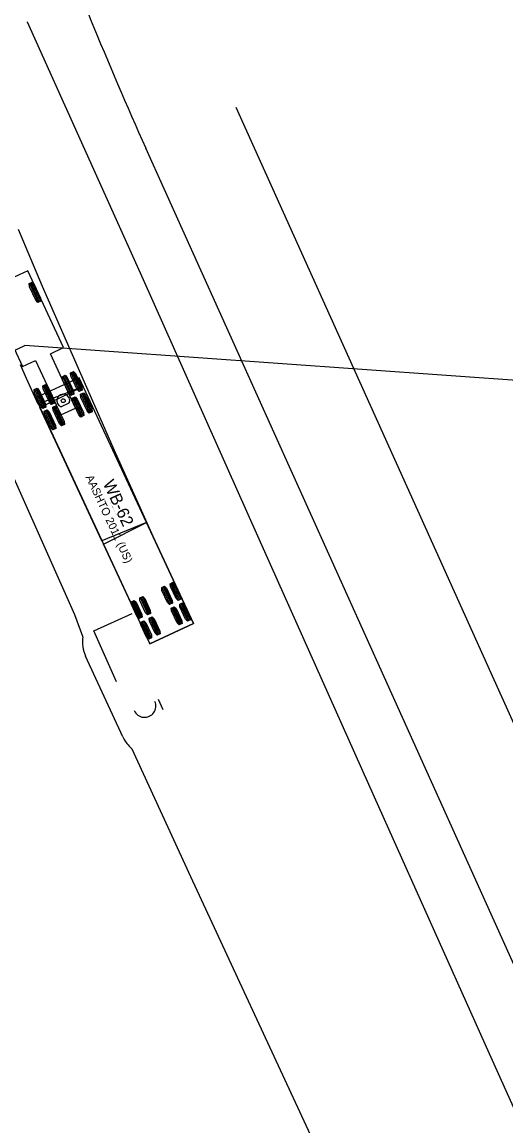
# Model space of a CAD drawing. Extents: x 2096670 to 2098561, y 684033 to 689893.
# Drawn here: x 2097772.9 to 2097858.5, y 685641.1 to 685836.6 of the extents above; entities that cross this region are included whole.
import ezdxf

# ---------------------------------------------------------------- set-up
doc = ezdxf.new("R2010")
doc.units = 0
for name, color, linetype in [('Old_Level_63', 7, 'Continuous'), ('Prop Conc 5in Monolithic Keyed In Island', 7, 'Continuous'), ('Prop DSN Text', 7, 'Continuous'), ('Prop EOT', 7, 'Continuous'), ('Prop Guardrail', 7, 'Continuous'), ('Prop Sign E Signal Light Ahead CELL', 7, 'Continuous'), ('Scratch_Level_4', 7, 'Continuous'), ('Scratch_Level_7', 7, 'Continuous')]:
    doc.layers.add(name, color=color, linetype=linetype)

msp = doc.modelspace()

# ---------------------------------------------------------------- linework, layer by layer
at = {"layer": 'Old_Level_63'}
for p, q in [((2097773.91, 685792.52), (2097766.65, 685789.15)), ((2097780.22, 685778.92), (2097773.91, 685792.52)), ((2097774.19, 685790.27), (2097775.74, 685786.94)), ((2097774.4, 685790.36), (2097775.95, 685787.04)), ((2097774.61, 685790.46), (2097776.15, 685787.13)), ((2097766.65, 685789.15), (2097772.97, 685775.55)), ((2097777.9, 685777.84), (2097780.22, 685778.92)), ((2097772.97, 685775.55), (2097775.3, 685776.63)), ((2097775.3, 685776.63), (2097779.76, 685767.01)), ((2097782.36, 685768.22), (2097777.9, 685777.84)), ((2097781.52, 685774.49), (2097783.07, 685771.16)), ((2097781.73, 685774.58), (2097783.28, 685771.26)), ((2097781.94, 685774.68), (2097783.48, 685771.35)), ((2097782.98, 685773.58), (2097775.27, 685770)), ((2097776.6, 685772.2), (2097778.14, 685768.87)), ((2097776.8, 685772.29), (2097778.35, 685768.97)), ((2097777.01, 685772.39), (2097778.56, 685769.06)), ((2097780.03, 685773.79), (2097781.57, 685770.47)), ((2097780.24, 685773.89), (2097781.78, 685770.56)), ((2097780.44, 685773.98), (2097781.99, 685770.66)), ((2097803.2, 685730.05), (2097782.98, 685773.58)), ((2097775.1, 685771.5), (2097776.64, 685768.18)), ((2097775.31, 685771.6), (2097776.85, 685768.27)), ((2097775.52, 685771.7), (2097777.06, 685768.37)), ((2097783.29, 685770.68), (2097784.84, 685767.35)), ((2097783.5, 685770.77), (2097785.05, 685767.45)), ((2097783.71, 685770.87), (2097785.25, 685767.54)), ((2097775.27, 685770), (2097795.49, 685726.47)), ((2097775.27, 685770), (2097775.27, 685770)), ((2097778.37, 685768.39), (2097779.91, 685765.06)), ((2097778.57, 685768.48), (2097780.12, 685765.16)), ((2097778.78, 685768.58), (2097780.33, 685765.26)), ((2097779.78, 685768.45), (2097781.25, 685769.13)), ((2097781.8, 685769.98), (2097783.34, 685766.66)), ((2097782, 685770.08), (2097783.55, 685766.75)), ((2097782.21, 685770.17), (2097783.76, 685766.85)), ((2097776.87, 685767.69), (2097778.41, 685764.37)), ((2097777.08, 685767.79), (2097778.62, 685764.46)), ((2097777.28, 685767.89), (2097778.83, 685764.56)), ((2097779.76, 685767.01), (2097782.36, 685768.22)), ((2097799.14, 685737.15), (2097800.53, 685734.16)), ((2097799.35, 685737.25), (2097800.74, 685734.25)), ((2097799.56, 685737.34), (2097800.95, 685734.35)), ((2097797.64, 685736.45), (2097799.03, 685733.46)), ((2097797.85, 685736.55), (2097799.24, 685733.56)), ((2097798.06, 685736.65), (2097799.45, 685733.65)), ((2097792.26, 685733.95), (2097793.65, 685730.96)), ((2097792.47, 685734.05), (2097793.86, 685731.06)), ((2097792.68, 685734.15), (2097794.07, 685731.15)), ((2097793.76, 685734.65), (2097795.15, 685731.66)), ((2097793.97, 685734.75), (2097795.36, 685731.75)), ((2097794.17, 685734.84), (2097795.56, 685731.85)), ((2097800.82, 685733.52), (2097802.21, 685730.53)), ((2097801.03, 685733.62), (2097802.42, 685730.62)), ((2097801.24, 685733.71), (2097802.63, 685730.72)), ((2097795.65, 685731.12), (2097797.04, 685728.13)), ((2097795.86, 685731.21), (2097797.25, 685728.22)), ((2097799.33, 685732.83), (2097800.72, 685729.83)), ((2097799.54, 685732.92), (2097800.93, 685729.93)), ((2097799.74, 685733.02), (2097801.13, 685730.03)), ((2097793.95, 685730.33), (2097795.34, 685727.33)), ((2097794.15, 685730.42), (2097795.54, 685727.43)), ((2097794.36, 685730.52), (2097795.75, 685727.53)), ((2097795.44, 685731.02), (2097796.83, 685728.03)), ((2097795.49, 685726.47), (2097803.2, 685730.05))]:
    msp.add_line(p, q, dxfattribs=at)
for points in [[(2097772.22, 685799.88), (2097774.41, 685794.67), (2097776.47, 685789.82), (2097780.68, 685780.12), (2097789.36, 685760.37), (2097793.7, 685750.67), (2097796.02, 685745.55), (2097803.2, 685730.05), (2097795.49, 685726.47), (2097795.41, 685726.64), (2097795.41, 685726.64)], [(2097795.41, 685726.64), (2097787.29, 685744.12), (2097794.89, 685747.94), (2097787.01, 685744.72), (2097776.05, 685768.32), (2097783.69, 685772.04), (2097775.77, 685768.93), (2097773.69, 685773.45), (2097772.61, 685775.88)]]:
    msp.add_lwpolyline(points, dxfattribs=at)
for points in [[(2097774.14, 685790.24), (2097774.66, 685790.48), (2097775.03, 685790.09), (2097776.15, 685787.7), (2097776.21, 685787.16), (2097775.69, 685786.92), (2097775.31, 685787.31), (2097774.2, 685789.7)], [(2097781.47, 685774.46), (2097781.99, 685774.7), (2097782.36, 685774.31), (2097783.48, 685771.92), (2097783.54, 685771.38), (2097783.02, 685771.14), (2097782.64, 685771.53), (2097781.53, 685773.92)], [(2097776.54, 685772.17), (2097777.06, 685772.41), (2097777.44, 685772.02), (2097778.55, 685769.63), (2097778.61, 685769.09), (2097778.09, 685768.85), (2097777.72, 685769.24), (2097776.6, 685771.64)], [(2097779.98, 685773.77), (2097780.49, 685774.01), (2097780.87, 685773.61), (2097781.98, 685771.22), (2097782.04, 685770.68), (2097781.52, 685770.44), (2097781.15, 685770.83), (2097780.04, 685773.23)], [(2097775.05, 685771.48), (2097775.57, 685771.72), (2097775.94, 685771.33), (2097777.05, 685768.93), (2097777.11, 685768.39), (2097776.59, 685768.15), (2097776.22, 685768.55), (2097775.11, 685770.94)], [(2097781.74, 685769.96), (2097782.26, 685770.2), (2097782.64, 685769.81), (2097783.75, 685767.41), (2097783.81, 685766.87), (2097783.29, 685766.63), (2097782.92, 685767.03), (2097781.8, 685769.42)], [(2097783.24, 685770.65), (2097783.76, 685770.89), (2097784.13, 685770.5), (2097785.24, 685768.11), (2097785.3, 685767.57), (2097784.79, 685767.33), (2097784.41, 685767.72), (2097783.3, 685770.11)], [(2097778.31, 685768.36), (2097778.83, 685768.6), (2097779.2, 685768.21), (2097780.32, 685765.82), (2097780.38, 685765.28), (2097779.86, 685765.04), (2097779.49, 685765.43), (2097778.37, 685767.83)], [(2097776.82, 685767.67), (2097777.34, 685767.91), (2097777.71, 685767.52), (2097778.82, 685765.12), (2097778.88, 685764.58), (2097778.36, 685764.34), (2097777.99, 685764.74), (2097776.88, 685767.13)], [(2097799.09, 685737.12), (2097799.61, 685737.37), (2097799.96, 685737.02), (2097800.96, 685734.86), (2097801, 685734.37), (2097800.48, 685734.13), (2097800.13, 685734.48), (2097799.13, 685736.63)], [(2097797.59, 685736.43), (2097798.11, 685736.67), (2097798.46, 685736.32), (2097799.46, 685734.17), (2097799.5, 685733.68), (2097798.98, 685733.44), (2097798.63, 685733.78), (2097797.63, 685735.94)], [(2097792.21, 685733.93), (2097792.73, 685734.17), (2097793.08, 685733.83), (2097794.08, 685731.67), (2097794.12, 685731.18), (2097793.6, 685730.94), (2097793.25, 685731.28), (2097792.25, 685733.44)], [(2097793.71, 685734.63), (2097794.23, 685734.87), (2097794.58, 685734.52), (2097795.58, 685732.37), (2097795.62, 685731.87), (2097795.1, 685731.63), (2097794.75, 685731.98), (2097793.75, 685734.13)], [(2097800.77, 685733.5), (2097801.29, 685733.74), (2097801.64, 685733.39), (2097802.64, 685731.24), (2097802.68, 685730.74), (2097802.16, 685730.5), (2097801.81, 685730.85), (2097800.81, 685733.01)], [(2097795.39, 685731), (2097795.91, 685731.24), (2097796.26, 685730.89), (2097797.26, 685728.74), (2097797.3, 685728.25), (2097796.78, 685728), (2097796.43, 685728.35), (2097795.43, 685730.51)], [(2097799.28, 685732.8), (2097799.8, 685733.04), (2097800.15, 685732.7), (2097801.15, 685730.54), (2097801.19, 685730.05), (2097800.67, 685729.81), (2097800.32, 685730.16), (2097799.31, 685732.31)], [(2097793.9, 685730.3), (2097794.41, 685730.54), (2097794.77, 685730.2), (2097795.77, 685728.04), (2097795.8, 685727.55), (2097795.29, 685727.31), (2097794.93, 685727.66), (2097793.93, 685729.81)]]:
    msp.add_lwpolyline(points, close=True, dxfattribs=at)
msp.add_circle((2097780.18, 685769.52), 0.34, dxfattribs=at)
msp.add_arc((2097780.18, 685769.52), 1.14, 339.9115, 249.9115, dxfattribs=at)
at = {"layer": 'Prop Conc 5in Monolithic Keyed In Island'}
msp.add_arc((2097794.56, 685715.46), 2, 204.2309, 24.2309, dxfattribs=at)
at = {"layer": 'Prop DSN Text'}
msp.add_line((2097760.94, 685773.4), (2097773.38, 685779.3), dxfattribs=at)
at = {"layer": 'Prop EOT'}
msp.add_line((2097797.87, 685714.8), (2097797.05, 685716.63), dxfattribs=at)
at = {"layer": 'Prop Guardrail'}
msp.add_line((2097865.36, 685657.45), (2097794.79, 685814.25), dxfattribs=at)
msp.add_arc((2098415.1, 686093.44), 680.25, 200.05795, 204.23092, dxfattribs=at)
at = {"layer": 'Prop Sign E Signal Light Ahead CELL'}
msp.add_line((2097875.52, 685772.02), (2097773.38, 685779.3), dxfattribs=at)
at = {"layer": 'Scratch_Level_4'}
for p, q in [((2097794.35, 685790.92), (2097773.86, 685836.55)), ((2097889.53, 685646.39), (2097810.74, 685821.44)), ((2097790.71, 685710), (2097784.14, 685724.26))]:
    msp.add_line(p, q, dxfattribs=at)
for points in [[(2097783.66, 685727.72), (2097783.67, 685727.77), (2097782.2, 685731.63), (2097761.9, 685777.22), (2097741.89, 685821.93), (2097720.65, 685868.66)], [(2097835.25, 685699.31), (2097814.59, 685745.52), (2097794.36, 685790.9)], [(2097802.77, 685685.21), (2097792.38, 685707.83), (2097792.03, 685708.17)], [(2097918.23, 685516.37), (2097897.05, 685562.45), (2097876.09, 685608.28), (2097855.55, 685653.89), (2097835.25, 685699.31)], [(2097865.36, 685548.34), (2097844.55, 685594.16), (2097823.9, 685639.54), (2097802.77, 685685.19)]]:
    msp.add_lwpolyline(points, dxfattribs=at)
for centre, start, end in [((2097768.39, 685834.1), 24.1833, 24.3191), ((2097788.88, 685788.46), 24.0268, 24.1833), ((2097789.59, 685726.77), 170.9125, 204.7415), ((2097796.16, 685712.52), 204.7415, 226.4599), ((2097829.77, 685696.86), 24.08, 24.0881), ((2097808.22, 685687.71), 204.6673, 204.8309)]:
    msp.add_arc(centre, 6, start, end, dxfattribs=at)
at = {"layer": 'Scratch_Level_7'}
msp.add_lwpolyline([(2097789.62, 685719.75), (2097785.56, 685728.76), (2097792.36, 685731.83)], dxfattribs=at)

# ---------------------------------------------------------------- texts
at = {"layer": 'Old_Level_63'}
for s, height, p in [('AASHTO 2011 (US)', 1.4167, (2097784.11, 685755.99)), ('WB-62', 2.125, (2097787.15, 685754.91)), ('(c) 2023 Transoft Solutions, Inc. All rights reserved.', 0.085, (2097788.46, 685751.58))]:
    msp.add_text(s, height=height, rotation=294.9115, dxfattribs=at).set_placement(p)

doc.saveas('drawing.dxf')
